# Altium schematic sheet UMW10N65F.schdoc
size 127 x 101 mm
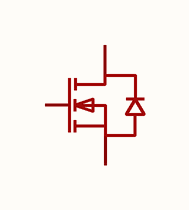
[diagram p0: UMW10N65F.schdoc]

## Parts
Q?  10n65f_c347323  [TO-220F-3_L10.2-W4.7-P2.54-L]  (value not drawn)

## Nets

Not connected (* = marked no-connect by the designer): Q? 1(G) 2(D) 3(S)

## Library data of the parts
Q? = 10n65f_c347323: 数量:1个N沟道;漏源电压(Vdss):650V;连续漏极电流(Id):10A;导通电阻(RDS(on)):750mΩ@10V;耗散功率(Pd):50W;阈值电压(Vgs(th)):4V;; Manufacturer: UMW(友台半导体); ManufacturerPart: 10N65F; Symbol: UMW10N65F; AddInBom: yes; ModelId: b5990cdf67854b65a85fdb5429325fb8; ModelTransform: 399.999,185.039,0,0,0,0,0,10.354,-118.11; Number: 1个N沟道; Drain to Source Voltage: 650V; Current - Continuous Drain(Id): 10A; Pd - Power Dissipation: 50W; Gate Threshold Voltage (Vgs(th)): 4V; Gate Charge(Qg): 45nC@10V; Input Capacitance(Ciss): 1.57nF; Type: N沟道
